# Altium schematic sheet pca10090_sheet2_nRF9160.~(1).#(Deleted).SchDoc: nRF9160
size A3; Organization: Nordic Semiconductor; DocumentNumber: 2; SheetNumber: 2; SheetTotal: 8; CompanyName: Nordic Semiconductor; DocumentSize: A3
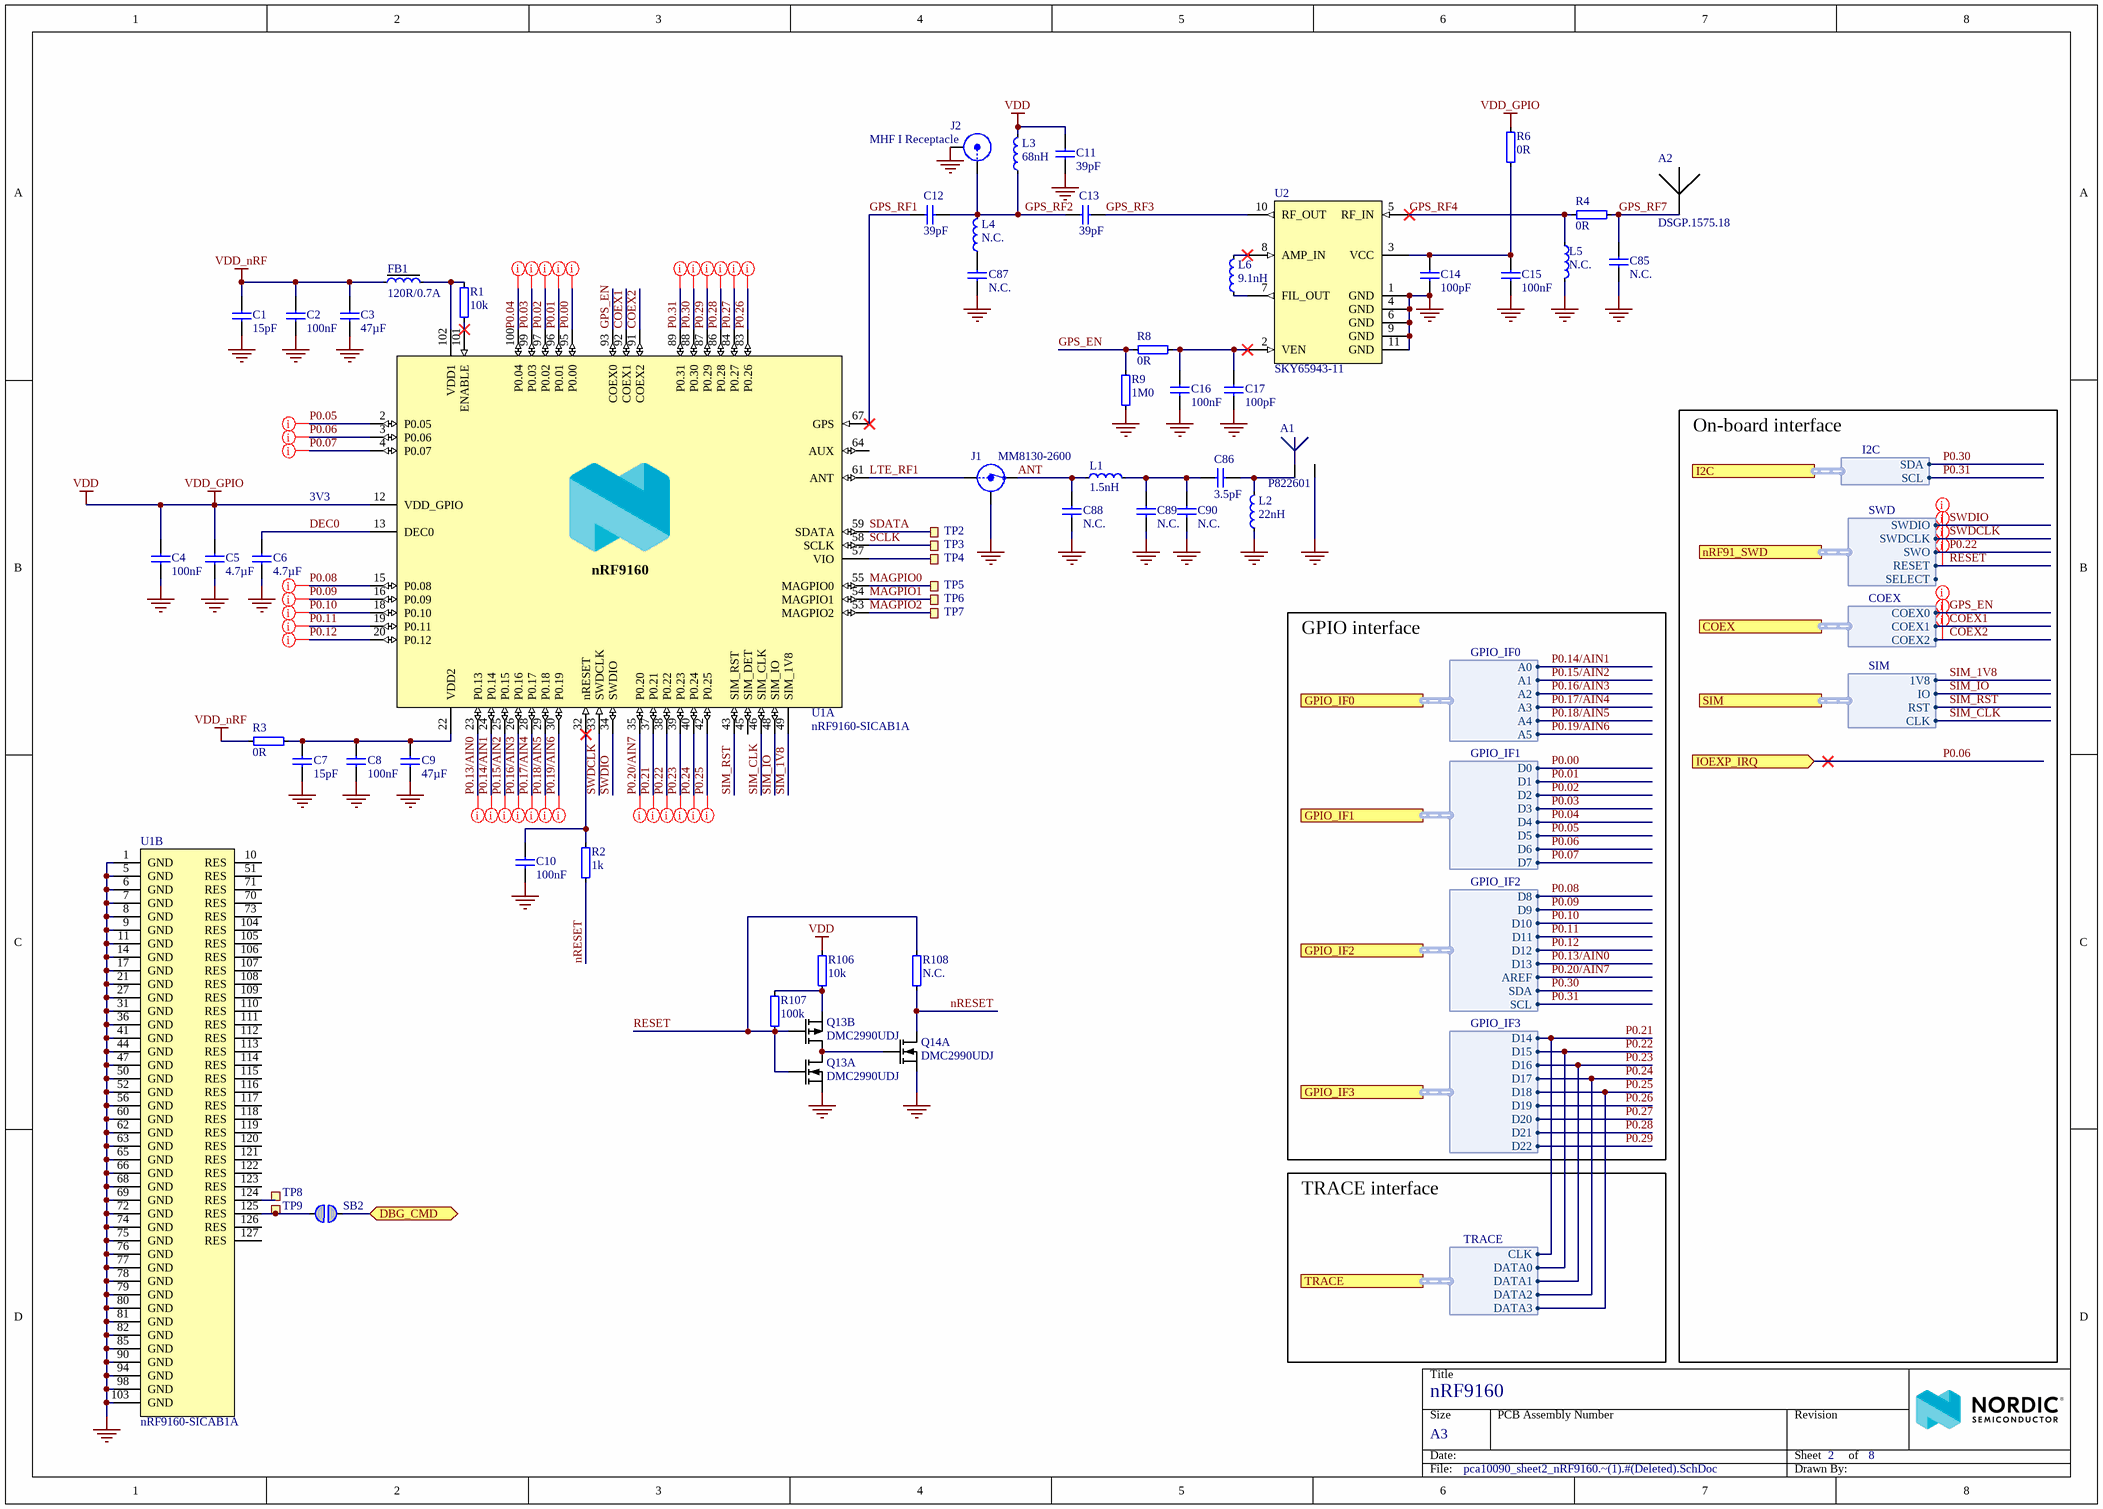
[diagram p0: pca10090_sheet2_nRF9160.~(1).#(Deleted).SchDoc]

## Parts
A1  P822601  [P822601]
A2  DSGP.1575.18  [DSGP.1575.18]
C1  15pF  [CAPC0603X03L_C]
C2  100nF  [CAPC0603X03L_C]
C3  47µF  [CAPC2012X11L]
C4  100nF  [CAPC0603X03L_C]
C5  4.7µF  [CAPC1005X04L]
C6  4.7µF  [CAPC2012X11L]
C7  15pF  [CAPC0603X03L_C]
C8  100nF  [CAPC0603X03L_C]
C9  47µF  [CAPC2012X11L]
C10  100nF  [CAPC0603X03L_C]
C11  39pF  [CAPC0603X03L_C]
C12  39pF  [CAPC0603X03L_C]
C13  39pF  [CAPC0603X03L_C]
C14  100pF  [CAPC0603X03L_C]
C15  100nF  [CAPC0603X03L_C]
C16  100nF  [CAPC0603X03L_C]
C17  100pF  [CAPC0603X03L_C]
C85  N.C.  [CAPC1005X04L_NC]
C86  3.5pF  [CAPC0603X03L_C]
C87  N.C.  [CAPC0603X03L_C_NC]
C88  N.C.  [CAPC0603X03L_C_NC]
C89  N.C.  [CAPC0603X03L_C_NC]
C90  N.C.  [CAPC0603X03L_C_NC]
FB1  120R/0.7A  [INDC1005X04L]
J1  MM8130-2600  [COAXIAL-SWF]
J2  MHF I Receptacle  [COAXIAL RF U.FL-R-SMT-1]
L1  1.5nH  [INDC0603X03L_C]
L2  22nH  [INDC0603X03L_C]
L3  68nH  [INDC1005X04L_WW]
L4  N.C.  [INDC1005X04L_NC]
L5  N.C.  [INDC1005X04L_NC]
L6  9.1nH  [INDC1005X04L_WW]
Q13  DMC2990UDJ  [SOTFL35P100X50-6N]  (parts A,B of 2)
Q14  DMC2990UDJ  [SOTFL35P100X50-6N]  (part A of 2)
R1  10k  [RESC0603X03L_C]
R2  1k  [RESC0603X03L_C]
R3  0R  [RESC0603X03L_C]
R4  0R  [RESC1005X04L]
R6  0R  [RESC0603X03L_C]
R8  0R  [RESC0603X03L_C]
R9  1M0  [RESC0603X03L_C]
R106  10k  [RESC0603X03L_C]
R107  100k  [RESC0603X03L_C]
R108  N.C.  [RESC0603X03L_C_NC]
SB2  Solderbridge  [Solderbridge]  (value not drawn)  (no BOM)
TP2  Ø1.0mm,SMD  [TP_SMD_D1.0mm]  (value not drawn)  (no BOM)
TP3  Ø1.0mm,SMD  [TP_SMD_D1.0mm]  (value not drawn)  (no BOM)
TP4  Ø1.0mm,SMD  [TP_SMD_D1.0mm]  (value not drawn)  (no BOM)
TP5  Ø1.0mm,SMD  [TP_SMD_D1.0mm]  (value not drawn)  (no BOM)
TP6  Ø1.0mm,SMD  [TP_SMD_D1.0mm]  (value not drawn)  (no BOM)
TP7  Ø1.0mm,SMD  [TP_SMD_D1.0mm]  (value not drawn)  (no BOM)
TP8  Ø1.0mm,SMD  [TP_SMD_D1.0mm]  (value not drawn)  (no BOM)
TP9  Ø1.0mm,SMD  [TP_SMD_D1.0mm]  (value not drawn)  (no BOM)
U1  nRF9160-SICAB1A  [LGA50P1600X1050X104-161N]  (parts A,B of 2)
U2  SKY65943-11  [SKY65943-11]

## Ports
COEX (harness COEX), DBG_CMD (bidir), GPIO_IF0 (harness GPIO_IF0), GPIO_IF1 (harness GPIO_IF1), GPIO_IF2 (harness GPIO_IF2), GPIO_IF3 (harness GPIO_IF3), I2C (harness I2C), IOEXP_IRQ (in), nRF91_SWD (harness SWD), SIM (harness SIM), TRACE (harness TRACE)

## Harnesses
COEX: COEX0, COEX2, COEX1
SIM: CLK, IO, 1V8, RST
SWD: SWDIO, SWDCLK, SWO, RESET, SELECT
I2C: SCL, SDA
GPIO_IF1: D0, D1, D2, D3, D4, D5, D6, D7
GPIO_IF2: D8, D9, D10, D11, D12, D13, AREF, SDA, SCL
GPIO_IF0: A0, A1, A2, A3, A4, A5
GPIO_IF3: D14, D15, D16, D17, D18, D19, D20, D21, D22
TRACE: CLK, DATA0, DATA1, DATA3, DATA2

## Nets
GND: A1.2 A2.2(GND) C1.2 C2.2 C3.2 C4.2 C5.2 C6.2 C7.2 C8.2 C9.2 C10.2 C11.1 C14.1 C15.1 C16.1 C17.1 C85.2 C87.1 C88.1 C89.1 C90.1 J1.2(Shield) J2.2(Y) L2.1 L5.2 Q13.1(S1) Q14.1(S1) R9.1 U1.1(GND) U1.5(GND) U1.6(GND) U1.7(GND) U1.8(GND) U1.9(GND) U1.11(GND) U1.14(GND) U1.17(GND) U1.21(GND) U1.27(GND) U1.31(GND) U1.36(GND) U1.41(GND) U1.44(GND) U1.47(GND) U1.50(GND) U1.52(GND) U1.56(GND) U1.60(GND) U1.62(GND) U1.63(GND) U1.65(GND) U1.66(GND) U1.68(GND) U1.69(GND) U1.72(GND) U1.74(GND) U1.75(GND) U1.76(GND) U1.77(GND) U1.78(GND) U1.79(GND) U1.80(GND) U1.81(GND) U1.82(GND) U1.85(GND) U1.90(GND) U1.94(GND) U1.98(GND) U1.103(GND) U2.1(GND) U2.4(GND) U2.6(GND) U2.9(GND) U2.11(GND)
VDD: C4.1 C5.1 C11.2 L3.1 R6.2 R106.1 U1.12(VDD_GPIO)  [also labelled VDD_GPIO]
VDD_nRF: C1.1 C2.1 C3.1 FB1.1 R3.1
ANT: C88.2 J1.3(OUT) L1.1
COEX1: U1.92(COEX1) ; port COEX.COEX1
COEX2: U1.91(COEX2) ; port COEX.COEX2
DBG_CMD: SB2.1 ; port DBG_CMD
DEC0: C6.1 U1.13(DEC0)
GPS_EN: R8.1 R9.2 U1.93(COEX0) ; port COEX.COEX0
GPS_RF1: C12.2 U1.67(GPS)
GPS_RF2: C12.1 C13.2 J2.1(X) L3.2 L4.1
GPS_RF3: C13.1 U2.10(RF_OUT)
GPS_RF4: L5.1 R4.1 U2.5(RF_IN)
GPS_RF7: A2.1 C85.1 R4.2
LTE_RF1: J1.1(IN) U1.61(ANT)
MAGPIO0: TP5.1 U1.55(MAGPIO0)
MAGPIO1: TP6.1 U1.54(MAGPIO1)
MAGPIO2: TP7.1 U1.53(MAGPIO2)
nRESET: Q14.6(D1) R2.1 R108.2
P0.00: U1.95(P0.00) ; port GPIO_IF1.D0
P0.01: U1.96(P0.01) ; port GPIO_IF1.D1
P0.02: U1.97(P0.02) ; port GPIO_IF1.D2
P0.03: U1.99(P0.03) ; port GPIO_IF1.D3
P0.04: U1.100(P0.04) ; port GPIO_IF1.D4
P0.05: U1.2(P0.05) ; port GPIO_IF1.D5
P0.06: U1.3(P0.06) ; port IOEXP_IRQ, port GPIO_IF1.D6
P0.07: U1.4(P0.07) ; port GPIO_IF1.D7
P0.08: U1.15(P0.08) ; port GPIO_IF2.D8
P0.09: U1.16(P0.09) ; port GPIO_IF2.D9
P0.10: U1.18(P0.10) ; port GPIO_IF2.D10
P0.11: U1.19(P0.11) ; port GPIO_IF2.D11
P0.12: U1.20(P0.12) ; port GPIO_IF2.D12
P0.13/AIN0: U1.23(P0.13) ; port GPIO_IF2.D13
P0.14/AIN1: U1.24(P0.14) ; port GPIO_IF0.A0
P0.15/AIN2: U1.25(P0.15) ; port GPIO_IF0.A1
P0.16/AIN3: U1.26(P0.16) ; port GPIO_IF0.A2
P0.17/AIN4: U1.28(P0.17) ; port GPIO_IF0.A3
P0.18/AIN5: U1.29(P0.18) ; port GPIO_IF0.A4
P0.19/AIN6: U1.30(P0.19) ; port GPIO_IF0.A5
P0.20/AIN7: U1.35(P0.20) ; port GPIO_IF2.AREF
P0.21: U1.37(P0.21) ; port GPIO_IF3.D14, port TRACE.CLK
P0.22: U1.38(P0.22) ; port nRF91_SWD.SWO, port GPIO_IF3.D15, port TRACE.DATA0
P0.23: U1.39(P0.23) ; port GPIO_IF3.D16, port TRACE.DATA1
P0.24: U1.40(P0.24) ; port GPIO_IF3.D17, port TRACE.DATA2
P0.25: U1.42(P0.25) ; port GPIO_IF3.D18, port TRACE.DATA3
P0.26: U1.83(P0.26) ; port GPIO_IF3.D19
P0.27: U1.84(P0.27) ; port GPIO_IF3.D20
P0.28: U1.86(P0.28) ; port GPIO_IF3.D21
P0.29: U1.87(P0.29) ; port GPIO_IF3.D22
P0.30: U1.88(P0.30) ; port I2C.SDA, port GPIO_IF2.SDA
P0.31: U1.89(P0.31) ; port I2C.SCL, port GPIO_IF2.SCL
RESET: Q13.2(G1) Q13.5(G2) R107.1 R108.1 ; port nRF91_SWD.RESET
SCLK: TP3.1 U1.58(SCLK)
SDATA: TP2.1 U1.59(SDATA)
SIM_1V8: U1.49(SIM_1V8) ; port SIM.1V8
SIM_CLK: U1.46(SIM_CLK) ; port SIM.CLK
SIM_IO: U1.48(SIM_IO) ; port SIM.IO
SIM_RST: U1.43(SIM_RST) ; port SIM.RST
SWDCLK: U1.33(SWDCLK) ; port nRF91_SWD.SWDCLK
SWDIO: U1.34(SWDIO) ; port nRF91_SWD.SWDIO
NetA1_1: A1.1 C86.2 L2.2
NetC7_1: C7.1 C8.1 C9.1 R3.2 U1.22(VDD2)
NetC10_1: C10.1 R2.2 U1.32(nRESET)
NetC14_2: C14.2 C15.2 R6.1 U2.3(VCC)
NetC16_2: C16.2 C17.2 R8.2 U2.2(VEN)
NetC86_1: C86.1 C89.2 C90.2 L1.2
NetC87_2: C87.2 L4.2
NetFB1_2: FB1.2 R1.1 U1.102(VDD1)
NetL6_1: L6.1 U2.8(AMP_IN)
NetL6_2: L6.2 U2.7(FIL_OUT)
NetQ13_3: Q13.3(D2) Q13.6(D1) Q14.2(G1)
NetQ13_4: Q13.4(S2) R106.2 R107.2
NetR1_2: R1.2 U1.101(ENABLE)
NetSB2_2: SB2.2 TP9.1 U1.125(RES)
NetTP4_1: TP4.1 U1.57(VIO)
NetTP8_1: TP8.1 U1.124(RES)

Not connected (* = marked no-connect by the designer): U1 10(RES) 45(SIM_DET) 51(RES) 64(AUX) 70(RES) 71(RES) 73(RES) 104(RES) 105(RES) 106(RES) 107(RES) 108(RES) 109(RES) 110(RES) 111(RES) 112(RES) 113(RES) 114(RES) 115(RES) 116(RES) 117(RES) 118(RES) 119(RES) 120(RES) 121(RES) 122(RES) 123(RES) 126(RES) 127(RES)

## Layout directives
net class GPIO: P0.00, P0.01, P0.02, P0.03, P0.04, P0.05, P0.06, P0.07, P0.08, P0.09, P0.10, P0.11, P0.12, P0.13/AIN0, P0.14/AIN1, P0.15/AIN2, P0.16/AIN3, P0.17/AIN4, P0.18/AIN5, P0.19/AIN6, P0.20/AIN7, P0.21, P0.22, P0.23, P0.24, P0.25, P0.26, P0.27, P0.28, P0.29, P0.30, P0.31
net class SWD: P0.22, RESET, SWDCLK, SWDIO
net class COEX: COEX1, COEX2, GPS_EN

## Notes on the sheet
- On-board interface
- 3V3
- GPIO interface
- TRACE interface

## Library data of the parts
A1 = P822601: ANTENNA PRESTTA OCTABAND LTE; Manufacturer: Ethertronics; Part number IPS: 00000009001; Note: N.A.; Pad Count: 2
A2 = DSGP.1575.18.4.A.02: 18 x 18 mm Low Profile GPS L1 / GALILEO E1 Passive Patch Antenna; Manufacturer: Taoglas; Part number IPS: 00000004435; Note: N.A.; Pad Count: 2
C1 C7 = C0201-15p: Capacitor, NP0, ±5%, 25V; Manufacturer: Murata; Manufacturer Part Number: GRM0335C1E150JD03D; Part number IPS: 00000003193; Artikkelnr Noca: N.A.; Pad Count: 2
C2 C4 C8 C10 C15 C16 = C0201-100n: Capacitor, X5R, ±10%; Manufacturer: N.A.; Part number IPS: 00000001248, 00000002505; Note: 16V; Pad Count: 2
C3 C9 = C0805-47µ-10V: Capacitor, X5R, ±20%, 10V; Manufacturer: Murata; Manufacturer Part Number: GRM21BR61A476ME15; Part number IPS: 00000004759; Artikkelnr Noca: N.A.; Pad Count: 2
C5 = C0402-4µ7: Capacitor, X5R, ±20%; Manufacturer: N.A.; Part number IPS: 00000001251, 00000007165; Note: 10V; Artikkelnr Noca: 20039482; Pad Count: 2
C6 = C0805-4µ7: Capacitor, X5R, ±10%, 16V; Manufacturer: N.A.; Part number IPS: 00000006289; Artikkelnr Noca: 20039266; Pad Count: 2
C11-C13 = C0201-39p: Capacitor, NP0, ±1%, 25V; Manufacturer: Murata; Manufacturer Part Number: GRM0335C1E390FA01; Part number IPS: 00000001668; Artikkelnr Noca: N.A.; Pad Count: 2
C14 C17 = C0201-100p: Capacitor, NP0, ±2%, 25V; Manufacturer: Murata; Manufacturer Part Number: GRM0335C1E101GA01; Part number IPS: 00000007853; Artikkelnr Noca: N.A.; Pad Count: 2
C85 = C0402-N.C.: Not mounted; Manufacturer: N.A.; Assembly: Not mounted; Note: Chip Cap; Pad Count: 2
C86 = C0201-3.5p: Capacitor, NP0, ±0.1pF, 25V; Manufacturer: Murata; Manufacturer Part Number: GJM0335C1H3R5BB01E; Part number IPS: 00000001469; Artikkelnr Noca: N.A.; Pad Count: 2
C87 = C0201-N.C.: Not mounted; Manufacturer: N.A.; Assembly: Not mounted; Note: Chip Cap; Pad Count: 2
C88-C90 = C0201-N.C.: Not mounted; Manufacturer: N.A.; Note: Chip Cap; Assembly: Not mounted; Pad Count: 2
FB1 = FB0402-120R@100M-700mA: Ferrite Bead, 120 Ohm @ 100MHz, 700mA, 130 mOhm Max; Manufacturer: Murata; Manufacturer Part Number: BLM15AX121SN1; Part number IPS: 00000004487; Note: N.A.; Pad Count: 2
J1 = MM8130-2600: Coaxial Connector with Switch; Manufacturer: Murata; Part number IPS: 00000009955; Note: N.A.; Artikkelnr Noca: 55029011; Pad Count: 3
J2 = 20279-001E-03: Ultraminiature Coaxial Connector, 50 Ohm, SMD; Manufacturer: Wellshow; Part number IPS: 00000004436; Note: N.A.; Pad Count: 3
L1 = L0201-1n5: Inductor, 650mA, ±0.1nH; Manufacturer: Murata; Manufacturer Part Number: LQP03TQ1N5B02D; Part number IPS: 00000000836; Note: N.A.; Pad Count: 2
L2 = L0201-22n: Chip Inductor; Manufacturer: N.A.; Part number IPS: 00000001478; Note: High frequency chip inductor ±10%; Pad Count: 2
L3 = L0402-68n-Wirewound-Murata: Inductor, 140mA, ±2%, 1960mΩ, Q=20; Manufacturer: Murata; Manufacturer Part Number: LQW15AN68NG00; Part number IPS: 00000002494; Note: -55°C ~ 125°C; Artikkelnr Noca: N.A.; Pad Count: 2
L4 L5 = L0402-N.C.: Not mounted; Manufacturer: N.A.; Assembly: Not mounted; Pad Count: 2
L6 = L0402-9n1-Wirewound-Murata: Inductor, 540mA, ±2%, 140mΩ, Q=25; Manufacturer: Murata; Manufacturer Part Number: LQW15AN9N1G00; Part number IPS: 00000002497; Note: -55°C ~ 125°C; Artikkelnr Noca: N.A.; Pad Count: 2
Q13 Q14 = DMC2990UDJ-7: MOSFET, Dual N and P-Channel, 20V, 450mA/310mA, 990mOhm, 350mW; Manufacturer: Diodes Incorporated; Part number IPS: 00000004489; Note: N.A.; Pad Count: 6
R1 R106 = R0201-10k: Resistor, ±1%, 0.05W; Manufacturer: N.A.; Part number IPS: 00000001255; Note: Chip Res 1%; Pad Count: 2
R2 = R0201-1k0: Resistor, ±1%, 0.05W; Manufacturer: N.A.; Part number IPS: 00000005786; Note: Chip Res 1%; Pad Count: 2
R3 R6 R8 = R0201-0R: Resistor, ±5%, 0.05W; Manufacturer: N.A.; Part number IPS: 00000003245; Note: Chip Res 5%; Pad Count: 2
R4 = R0402-0R: Resistor, ±5%, 0.063W; Manufacturer: N.A.; Part number IPS: 00000007128; Note: Chip Res 5%; Artikkelnr Noca: 27049000; Pad Count: 2
R9 = R0201-1M0: Resistor, ±1%, 0.05W; Manufacturer: N.A.; Part number IPS: 00000001418; Note: Chip Res 1%; Pad Count: 2
R107 = R0201-100k: Resistor, ±1%, 0.05W; Manufacturer: N.A.; Part number IPS: 00000001419; Note: Chip Res 1%; Pad Count: 2
R108 = R0201-N.C.: Not mounted; Manufacturer: N.A.; Note: Chip Res; Assembly: Not mounted; Pad Count: 2
SB2 = Solderbridge: Manufacturer: N.A.; Pad Count: 2
TP2-TP9 = TP_SMD_Ø1.0MM: 1.0mm circular SMD testpad; Manufacturer: Nordic Semiconductor; Manufacturer Part Number: N.A.; Pad Count: 1
U1 = nRF9160-SICAB1A: Low power System-in-Package with integrated LTE-M/NB-IoT modem and GPS; Manufacturer: Nordic Semiconductor; Part number IPS: 80000002329; Note: N.A.; Pad Count: 161
U2 = SKY65943-11: GNSS Low-Noise Amplifier Front-End Module with Integrated Pre-Filter and Post-Filter; Manufacturer: Skyworks; Part number IPS: 00000002997; Note: N.A.; Pad Count: 10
